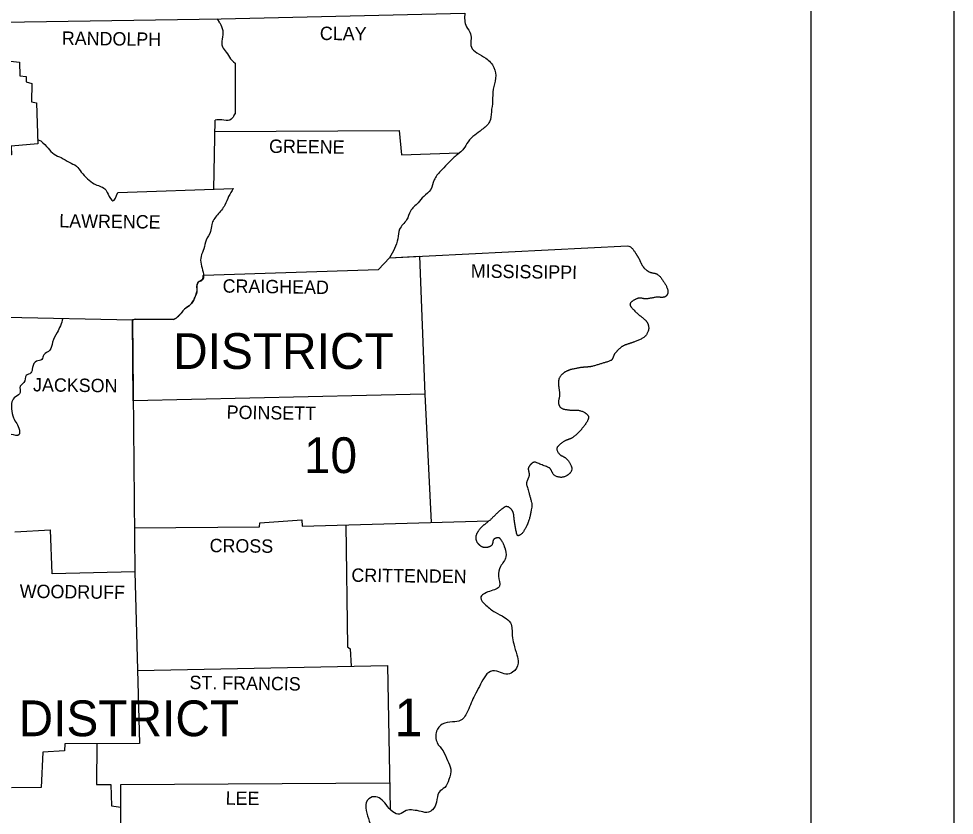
# Model space of a CAD drawing. Extents: x -0.54 to 1.64, y 0 to 0.92.
# Drawn here: x 1.2805 to 1.4167, y 0.7032 to 0.8191 of the extents above; entities that cross this region are included whole.
import ezdxf

# ---------------------------------------------------------------- set-up
doc = ezdxf.new("R2010")
doc.units = 0
for name, color, linetype in [('Default', 7, 'Continuous'), ('SHET_Annotations', 7, 'Continuous'), ('SHET_Border-Lines', 7, 'Continuous')]:
    doc.layers.add(name, color=color, linetype=linetype)

msp = doc.modelspace()

# ---------------------------------------------------------------- linework, layer by layer
at = {"layer": 'Default'}
msp.add_lwpolyline([(1.30741, 0.78176), (1.33287, 0.7826), (1.33448, 0.78431), (1.33888, 0.78453), (1.33964, 0.76447), (1.29721, 0.7635), (1.29711, 0.77526), (1.29752, 0.77536), (1.30307, 0.77533)], dxfattribs=at)
for points, degree in [([(1.3073, 0.78117), (1.30736, 0.78136), (1.3074, 0.78156), (1.30741, 0.78176)], 2), ([(1.30307, 0.77533), (1.30334, 0.77546), (1.30357, 0.77561), (1.30377, 0.7758), (1.30411, 0.77612), (1.30435, 0.77652), (1.30468, 0.77684), (1.30494, 0.77709), (1.30528, 0.77724), (1.30554, 0.77751), (1.30579, 0.77779), (1.30598, 0.7781), (1.30613, 0.77845), (1.30627, 0.77874), (1.30636, 0.77905), (1.30644, 0.77935), (1.30657, 0.77978), (1.30648, 0.78025), (1.3066, 0.78068), (1.30668, 0.78095), (1.30721, 0.78089), (1.3073, 0.78117)], 3)]:
    msp.add_open_spline(points, degree=degree, dxfattribs=at)
at = {"layer": 'SHET_Annotations'}
for p, q in [((1.30981, 0.81849), (1.30946, 0.81908)), ((1.31179, 0.81284), (1.31202, 0.81262)), ((1.31186, 0.80498), (1.31202, 0.80525)), ((1.28383, 0.80129), (1.28329, 0.80145)), ((1.31176, 0.79437), (1.31178, 0.79439)), ((1.27998, 0.74446), (1.28519, 0.74474))]:
    msp.add_line(p, q, dxfattribs=at)
for points in [[(1.09511, 0.81784), (1.16886, 0.81779), (1.23365, 0.81792), (1.31002, 0.81909), (1.34545, 0.81992)], [(1.27561, 0.81856), (1.27545, 0.81717), (1.27636, 0.81704), (1.27628, 0.81652), (1.27735, 0.81628), (1.27742, 0.81553), (1.27794, 0.81522), (1.27807, 0.81304), (1.28066, 0.81278), (1.28069, 0.81079), (1.28165, 0.81068), (1.28162, 0.8099), (1.28245, 0.80965), (1.28243, 0.807), (1.28313, 0.80687), (1.28331, 0.80091), (1.27945, 0.80054), (1.2795, 0.79927), (1.27833, 0.79919), (1.27872, 0.77567), (1.29711, 0.77526), (1.29742, 0.73864), (1.28541, 0.73833), (1.28519, 0.74474)], [(1.31202, 0.81262), (1.31202, 0.80525)], [(1.30892, 0.7943), (1.30914, 0.80435)], [(1.3091, 0.80269), (1.33588, 0.80282), (1.33624, 0.79927), (1.3446, 0.79956)], [(1.29495, 0.79383), (1.31178, 0.79439)], [(1.33448, 0.78431), (1.36913, 0.78605)], [(1.30741, 0.78176), (1.33287, 0.7826), (1.33448, 0.78431)], [(1.33888, 0.78453), (1.33964, 0.76447), (1.34056, 0.74579)], [(1.30307, 0.77533), (1.29752, 0.77536), (1.29711, 0.77526)], [(1.33964, 0.76447), (1.29721, 0.7635)], [(1.29736, 0.74504), (1.31557, 0.74515), (1.31562, 0.74577), (1.32174, 0.74621), (1.32177, 0.74528), (1.34896, 0.74602)], [(1.32812, 0.74545), (1.32838, 0.72769), (1.32877, 0.72741), (1.32894, 0.72492)], [(1.29742, 0.73864), (1.29812, 0.71366), (1.28725, 0.71361), (1.2872, 0.7126), (1.28406, 0.71239), (1.2838, 0.70723), (1.27948, 0.7072)], [(1.29782, 0.72429), (1.33419, 0.72502)], [(1.33419, 0.72502), (1.33457, 0.70412)], [(1.29192, 0.71363), (1.29184, 0.7077), (1.29394, 0.7077), (1.29405, 0.70456), (1.29542, 0.7044)], [(1.29192, 0.71363), (1.29184, 0.7077), (1.29394, 0.7077), (1.29405, 0.70456), (1.29542, 0.7044)], [(1.29727, 0.6672), (1.30154, 0.66747), (1.30152, 0.67671), (1.29814, 0.67697), (1.29833, 0.69507), (1.29547, 0.69548), (1.2954, 0.70767), (1.3345, 0.70793)]]:
    msp.add_lwpolyline(points, dxfattribs=at)
for points in [[(1.34545, 0.81992), (1.34568, 0.81792), (1.3463, 0.81688), (1.34641, 0.81496), (1.34719, 0.81413), (1.34851, 0.81333), (1.34968, 0.81198), (1.34994, 0.81042), (1.34957, 0.80884), (1.34949, 0.80708), (1.34931, 0.80552), (1.34905, 0.8041), (1.34794, 0.80295), (1.3469, 0.80215), (1.34594, 0.80119), (1.34527, 0.80015), (1.34405, 0.79906), (1.34288, 0.79792), (1.34192, 0.79691), (1.34099, 0.79564), (1.3405, 0.79424), (1.33948, 0.79323), (1.33865, 0.79232), (1.33754, 0.7911), (1.33699, 0.78983), (1.33596, 0.78846), (1.3357, 0.78708), (1.33448, 0.78431)], [(1.30981, 0.81849), (1.31023, 0.81737), (1.31015, 0.81613), (1.31018, 0.81501), (1.31075, 0.81421), (1.31137, 0.81325), (1.31179, 0.81284)], [(1.31186, 0.80498), (1.31127, 0.80435), (1.3101, 0.80438), (1.30914, 0.80435)], [(1.28383, 0.80129), (1.28481, 0.80026), (1.28572, 0.79938), (1.28671, 0.79888), (1.2879, 0.79821), (1.28894, 0.79764), (1.28964, 0.79678), (1.29057, 0.79582), (1.29153, 0.79507), (1.29306, 0.79434), (1.29355, 0.79357), (1.29425, 0.79261), (1.29495, 0.79383)], [(1.31176, 0.79437), (1.31109, 0.79325), (1.31054, 0.79198), (1.30945, 0.79056), (1.30862, 0.78913), (1.30847, 0.78815), (1.30782, 0.78688), (1.30748, 0.78563), (1.30707, 0.78452), (1.30707, 0.78337), (1.30738, 0.78223), (1.3073, 0.78117), (1.3066, 0.78068), (1.30644, 0.77935), (1.30613, 0.77845), (1.30554, 0.77751), (1.30468, 0.77684), (1.30377, 0.7758), (1.30307, 0.77533)], [(1.28698, 0.77549), (1.28614, 0.77342), (1.28546, 0.77204), (1.28507, 0.77085), (1.28419, 0.77017), (1.28391, 0.76953), (1.28315, 0.76927), (1.28256, 0.76836), (1.2823, 0.76755), (1.28165, 0.76719), (1.28131, 0.76615), (1.28074, 0.76561), (1.28077, 0.7647), (1.28009, 0.76408), (1.27955, 0.76335), (1.27952, 0.76232), (1.27978, 0.76102), (1.28025, 0.76021), (1.28064, 0.75923), (1.28061, 0.75858), (1.27947, 0.75858), (1.27849, 0.75843)], [(1.35126, 0.74211), (1.35144, 0.74082), (1.35064, 0.73939), (1.35035, 0.73799), (1.35051, 0.73656), (1.34905, 0.73578), (1.34776, 0.73485), (1.34851, 0.73379), (1.34986, 0.73275), (1.35123, 0.732), (1.35209, 0.73119), (1.35235, 0.72935), (1.35258, 0.72813), (1.35302, 0.72653), (1.3532, 0.72536), (1.3524, 0.72401), (1.35144, 0.72373), (1.3504, 0.72406), (1.34921, 0.72414), (1.34825, 0.72321), (1.34758, 0.72196), (1.3469, 0.72067), (1.34638, 0.71958), (1.34589, 0.71841), (1.34488, 0.71703), (1.34366, 0.7168), (1.34218, 0.71644), (1.34133, 0.71543), (1.34145, 0.71374), (1.34228, 0.71257), (1.34293, 0.71117), (1.3434, 0.70993), (1.34314, 0.7084), (1.34252, 0.70726), (1.34171, 0.70656), (1.34133, 0.7051), (1.34075, 0.70402), (1.34018, 0.70365), (1.33909, 0.70376), (1.33793, 0.70396), (1.33692, 0.70389), (1.33593, 0.70337), (1.33497, 0.7037), (1.33399, 0.70477), (1.33318, 0.7056), (1.33225, 0.70591), (1.33129, 0.70542), (1.33111, 0.70391), (1.33155, 0.70236), (1.33199, 0.70025), (1.33157, 0.69901), (1.33142, 0.69688)]]:
    msp.add_spline(points, degree=3, dxfattribs=at)
msp.add_open_spline([(1.36913, 0.78605), (1.3693, 0.78602), (1.36947, 0.78595), (1.36962, 0.78584), (1.36978, 0.78572), (1.3699, 0.78558), (1.37001, 0.78543), (1.37012, 0.78526), (1.37024, 0.78509), (1.37034, 0.78492), (1.37039, 0.78483), (1.37045, 0.78474), (1.3705, 0.78466), (1.37055, 0.78458), (1.3706, 0.78449), (1.37066, 0.78441), (1.37073, 0.7843), (1.37079, 0.78419), (1.37085, 0.78407), (1.3709, 0.78395), (1.37095, 0.78383), (1.37101, 0.78372), (1.37106, 0.7836), (1.37112, 0.78348), (1.37117, 0.78336), (1.37123, 0.78325), (1.3713, 0.78314), (1.37138, 0.78304), (1.37165, 0.78271), (1.37197, 0.78246), (1.37234, 0.78226), (1.37243, 0.78221), (1.37253, 0.78217), (1.37263, 0.78215), (1.37273, 0.78212), (1.37283, 0.7821), (1.37293, 0.78208), (1.37304, 0.78206), (1.37314, 0.78204), (1.37324, 0.78201), (1.37334, 0.78198), (1.37343, 0.78194), (1.37351, 0.78187), (1.37388, 0.78158), (1.37414, 0.78123), (1.37439, 0.78083), (1.37463, 0.78046), (1.37483, 0.78009), (1.37496, 0.77967), (1.37499, 0.77958), (1.375, 0.77949), (1.375, 0.77941), (1.375, 0.77932), (1.37499, 0.77923), (1.37497, 0.77913), (1.37494, 0.77904), (1.37491, 0.77896), (1.37486, 0.77888), (1.37483, 0.77884), (1.3748, 0.7788), (1.37477, 0.77877), (1.37475, 0.77875), (1.37473, 0.77874), (1.37471, 0.77872), (1.37469, 0.77871), (1.37467, 0.77869), (1.37465, 0.77868), (1.37455, 0.77862), (1.37444, 0.77858), (1.37433, 0.77856), (1.37422, 0.77855), (1.37411, 0.77855), (1.374, 0.77855), (1.37389, 0.77856), (1.37379, 0.77858), (1.37368, 0.77858), (1.37362, 0.77859), (1.37357, 0.77859), (1.37351, 0.77859), (1.37346, 0.77859), (1.37341, 0.77859), (1.37335, 0.77858), (1.37312, 0.77854), (1.37289, 0.7785), (1.37265, 0.77846), (1.37242, 0.77842), (1.37219, 0.77838), (1.37195, 0.77834), (1.37184, 0.77833), (1.37173, 0.77833), (1.37162, 0.77835), (1.37151, 0.77836), (1.37139, 0.77839), (1.37128, 0.77841), (1.37117, 0.77842), (1.37106, 0.77844), (1.37094, 0.77845), (1.37089, 0.77845), (1.37083, 0.77845), (1.37077, 0.77844), (1.37072, 0.77843), (1.37066, 0.77841), (1.3706, 0.77839), (1.37047, 0.77835), (1.37035, 0.77829), (1.37022, 0.77823), (1.37009, 0.77817), (1.36996, 0.77809), (1.36984, 0.77801), (1.36974, 0.77794), (1.36965, 0.77786), (1.36957, 0.77776), (1.36953, 0.77772), (1.36951, 0.77767), (1.3695, 0.77762), (1.36949, 0.7776), (1.36949, 0.77758), (1.36949, 0.77755), (1.36948, 0.77753), (1.36948, 0.77751), (1.36949, 0.77749), (1.36952, 0.77738), (1.36956, 0.77728), (1.36963, 0.77718), (1.36971, 0.77707), (1.36979, 0.77697), (1.36988, 0.77687), (1.37008, 0.77667), (1.37029, 0.77646), (1.3705, 0.77627), (1.37061, 0.77617), (1.37072, 0.77607), (1.37083, 0.77598), (1.37094, 0.77589), (1.37106, 0.7758), (1.37117, 0.77571), (1.37128, 0.77563), (1.37139, 0.77554), (1.37151, 0.77544), (1.37162, 0.77535), (1.37172, 0.77524), (1.37182, 0.77513), (1.3719, 0.77504), (1.37196, 0.77494), (1.37202, 0.77484), (1.37207, 0.77474), (1.37211, 0.77463), (1.37215, 0.77452), (1.37218, 0.77441), (1.3722, 0.7743), (1.3722, 0.77419), (1.37221, 0.77409), (1.37221, 0.77399), (1.37219, 0.77388), (1.37214, 0.77365), (1.37206, 0.77344), (1.37194, 0.77323), (1.37188, 0.77312), (1.3718, 0.77302), (1.37172, 0.77293), (1.37163, 0.77284), (1.37154, 0.77276), (1.37143, 0.77269), (1.37121, 0.77255), (1.37097, 0.77242), (1.37073, 0.77232), (1.37049, 0.77223), (1.37025, 0.77213), (1.37001, 0.77204), (1.36989, 0.772), (1.36977, 0.77195), (1.36965, 0.77191), (1.36952, 0.77187), (1.3694, 0.77183), (1.36928, 0.77179), (1.36916, 0.77175), (1.36904, 0.77171), (1.36891, 0.77167), (1.36879, 0.77163), (1.36867, 0.77158), (1.36856, 0.77152), (1.36843, 0.77146), (1.36831, 0.77139), (1.3682, 0.7713), (1.36809, 0.77122), (1.36798, 0.77113), (1.36788, 0.77103), (1.36778, 0.77093), (1.36769, 0.77082), (1.36759, 0.77072), (1.3675, 0.77062), (1.3674, 0.77051), (1.36731, 0.77041), (1.36724, 0.77033), (1.36719, 0.77024), (1.36715, 0.77014), (1.36711, 0.77004), (1.36708, 0.76994), (1.36704, 0.76984), (1.367, 0.76974), (1.36696, 0.76965), (1.36691, 0.76956), (1.36685, 0.76948), (1.36678, 0.76941), (1.36669, 0.76937), (1.36646, 0.76927), (1.36623, 0.76918), (1.36599, 0.76911), (1.36576, 0.76904), (1.36552, 0.76897), (1.36529, 0.7689), (1.36505, 0.76883), (1.36481, 0.76875), (1.36457, 0.76868), (1.36432, 0.76861), (1.36408, 0.76854), (1.36384, 0.76849), (1.36373, 0.76846), (1.36362, 0.76845), (1.36351, 0.76844), (1.36341, 0.76843), (1.3633, 0.76842), (1.36319, 0.76841), (1.36308, 0.7684), (1.36297, 0.7684), (1.36286, 0.76839), (1.36276, 0.76838), (1.36265, 0.76837), (1.36254, 0.76836), (1.3623, 0.76833), (1.36206, 0.76829), (1.36182, 0.76824), (1.36159, 0.7682), (1.36135, 0.76815), (1.36111, 0.7681), (1.36098, 0.76807), (1.36085, 0.76804), (1.36073, 0.768), (1.3606, 0.76796), (1.36048, 0.76791), (1.36036, 0.76786), (1.36024, 0.7678), (1.36012, 0.76774), (1.36, 0.76767), (1.35994, 0.76763), (1.35989, 0.76758), (1.35983, 0.76754), (1.35977, 0.7675), (1.35972, 0.76745), (1.35966, 0.7674), (1.35949, 0.76724), (1.35934, 0.76705), (1.35922, 0.76684), (1.35917, 0.76674), (1.35913, 0.76664), (1.35911, 0.76653), (1.35908, 0.76642), (1.35906, 0.76631), (1.35906, 0.76621), (1.35906, 0.76607), (1.35907, 0.76592), (1.35909, 0.76578), (1.3591, 0.76564), (1.35912, 0.7655), (1.35914, 0.76536), (1.35916, 0.76522), (1.35918, 0.76508), (1.3592, 0.76494), (1.35922, 0.7648), (1.35924, 0.76466), (1.35925, 0.76452), (1.35925, 0.76437), (1.35923, 0.76423), (1.35921, 0.76408), (1.35919, 0.76393), (1.35914, 0.76379), (1.35912, 0.76364), (1.35909, 0.76349), (1.35908, 0.76334), (1.35908, 0.7632), (1.35909, 0.76312), (1.3591, 0.76305), (1.35912, 0.76298), (1.35913, 0.76294), (1.35915, 0.7629), (1.35916, 0.76287), (1.35918, 0.76283), (1.3592, 0.76279), (1.35922, 0.76276), (1.35929, 0.76263), (1.35939, 0.76253), (1.35951, 0.76245), (1.35963, 0.76237), (1.35976, 0.76232), (1.35989, 0.76229), (1.36003, 0.76226), (1.36017, 0.76224), (1.36031, 0.76222), (1.36045, 0.7622), (1.36058, 0.76218), (1.36072, 0.76216), (1.36083, 0.76215), (1.36094, 0.76213), (1.36105, 0.76213), (1.36116, 0.76213), (1.36127, 0.76214), (1.36139, 0.76214), (1.3615, 0.76214), (1.36161, 0.76214), (1.36172, 0.76214), (1.36183, 0.76215), (1.36194, 0.76213), (1.36205, 0.76211), (1.36229, 0.76206), (1.36253, 0.76198), (1.36275, 0.76187), (1.36287, 0.76182), (1.36297, 0.76175), (1.36307, 0.76167), (1.36312, 0.76164), (1.36317, 0.76159), (1.36321, 0.76155), (1.36326, 0.76151), (1.3633, 0.76146), (1.36334, 0.76141), (1.3634, 0.76134), (1.36343, 0.76125), (1.36344, 0.76117), (1.36346, 0.76108), (1.36345, 0.76099), (1.36342, 0.7609), (1.36336, 0.76072), (1.36329, 0.76055), (1.36319, 0.7604), (1.36304, 0.76018), (1.3629, 0.75996), (1.36274, 0.75976), (1.36266, 0.75965), (1.36258, 0.75955), (1.36249, 0.75945), (1.36241, 0.75935), (1.36232, 0.75925), (1.36223, 0.75915), (1.36189, 0.75878), (1.36152, 0.75844), (1.36111, 0.75814), (1.36103, 0.75808), (1.36094, 0.75803), (1.36084, 0.75799), (1.36075, 0.75795), (1.36065, 0.75792), (1.36055, 0.75788), (1.36046, 0.75785), (1.36036, 0.75782), (1.36026, 0.75778), (1.36016, 0.75775), (1.36006, 0.7577), (1.35997, 0.75765), (1.35975, 0.75752), (1.35955, 0.75737), (1.35935, 0.75721), (1.35925, 0.75713), (1.35917, 0.75705), (1.35909, 0.75696), (1.35901, 0.75688), (1.35894, 0.75679), (1.35888, 0.75669), (1.35881, 0.75655), (1.35884, 0.75635), (1.35891, 0.7562), (1.359, 0.75603), (1.3591, 0.75586), (1.35925, 0.75573), (1.35932, 0.75566), (1.35939, 0.75559), (1.35948, 0.75554), (1.35957, 0.7555), (1.35966, 0.75545), (1.35974, 0.75541), (1.35983, 0.75536), (1.35991, 0.75531), (1.36, 0.75526), (1.36009, 0.75522), (1.36016, 0.75515), (1.36023, 0.75508), (1.36054, 0.75478), (1.36076, 0.75442), (1.36091, 0.75404), (1.36102, 0.75375), (1.36102, 0.75335), (1.36083, 0.75308), (1.36079, 0.75303), (1.36075, 0.75299), (1.36071, 0.75295), (1.36067, 0.7529), (1.36063, 0.75286), (1.36058, 0.75283), (1.3605, 0.75275), (1.36041, 0.75269), (1.36032, 0.75263), (1.36014, 0.75252), (1.35994, 0.75246), (1.35974, 0.75241), (1.35954, 0.75236), (1.35932, 0.75237), (1.35912, 0.7524), (1.35891, 0.75244), (1.35871, 0.75251), (1.35852, 0.75264), (1.35841, 0.75272), (1.35833, 0.7528), (1.35827, 0.75291), (1.35821, 0.75302), (1.35816, 0.75313), (1.3581, 0.75324), (1.35804, 0.75335), (1.35799, 0.75346), (1.35792, 0.75356), (1.35786, 0.75366), (1.35777, 0.75374), (1.35766, 0.75378), (1.35734, 0.75393), (1.357, 0.75404), (1.35668, 0.75417), (1.35638, 0.7543), (1.35609, 0.75444), (1.3558, 0.75456), (1.35571, 0.75459), (1.35562, 0.7546), (1.35553, 0.75458), (1.35544, 0.75455), (1.35535, 0.75451), (1.35527, 0.75445), (1.35518, 0.75439), (1.3551, 0.75432), (1.35503, 0.75424), (1.35499, 0.75419), (1.35495, 0.75415), (1.35491, 0.7541), (1.35488, 0.75406), (1.35484, 0.75401), (1.35481, 0.75396), (1.35475, 0.75387), (1.3547, 0.75375), (1.35469, 0.75364), (1.35469, 0.75353), (1.3547, 0.75342), (1.35472, 0.75331), (1.35475, 0.7532), (1.35478, 0.7531), (1.3548, 0.75299), (1.35481, 0.75293), (1.35481, 0.75288), (1.35482, 0.75283), (1.35482, 0.75277), (1.35482, 0.75272), (1.35481, 0.75267), (1.35479, 0.75254), (1.35475, 0.75243), (1.35471, 0.75231), (1.35466, 0.75219), (1.3546, 0.75207), (1.35456, 0.75195), (1.35451, 0.75184), (1.35447, 0.75172), (1.35444, 0.7516), (1.35442, 0.75148), (1.35442, 0.75136), (1.35445, 0.75124), (1.35455, 0.75089), (1.35466, 0.75053), (1.35476, 0.75018), (1.35489, 0.7497), (1.35503, 0.74923), (1.35515, 0.74875), (1.35524, 0.7484), (1.35518, 0.74802), (1.35512, 0.74766), (1.35503, 0.74713), (1.35492, 0.7466), (1.35476, 0.74608), (1.35471, 0.74594), (1.35467, 0.7458), (1.35461, 0.74566), (1.35455, 0.74552), (1.35449, 0.74539), (1.35443, 0.74526), (1.35436, 0.74512), (1.35429, 0.74499), (1.35421, 0.74486), (1.35414, 0.74473), (1.35406, 0.7446), (1.35398, 0.74447), (1.35386, 0.74428), (1.35369, 0.74414), (1.3535, 0.74399), (1.35341, 0.74393), (1.35332, 0.7439), (1.35323, 0.74388), (1.3532, 0.74387), (1.35317, 0.74387), (1.35313, 0.7439), (1.3531, 0.74392), (1.35308, 0.74395), (1.35307, 0.74398), (1.35299, 0.74426), (1.35291, 0.74455), (1.35286, 0.74484), (1.35281, 0.74513), (1.35275, 0.74542), (1.35271, 0.74572), (1.35268, 0.74595), (1.35265, 0.74618), (1.35263, 0.74642), (1.35261, 0.74653), (1.3526, 0.74665), (1.35258, 0.74677), (1.35257, 0.74689), (1.35255, 0.747), (1.35253, 0.74712), (1.35251, 0.7472), (1.35249, 0.74728), (1.35246, 0.74735), (1.35242, 0.74743), (1.35239, 0.7475), (1.35234, 0.74757), (1.35229, 0.74764), (1.35224, 0.7477), (1.35218, 0.74777), (1.35212, 0.74783), (1.35206, 0.74789), (1.35198, 0.74795), (1.35187, 0.74804), (1.35174, 0.74809), (1.35161, 0.7481), (1.35148, 0.74812), (1.35134, 0.7481), (1.35123, 0.74803), (1.35115, 0.74797), (1.35107, 0.74792), (1.35099, 0.74786), (1.35091, 0.7478), (1.35083, 0.74775), (1.35075, 0.74769), (1.35059, 0.74756), (1.35044, 0.74744), (1.3503, 0.7473), (1.35012, 0.74713), (1.34994, 0.74695), (1.34977, 0.74678), (1.34959, 0.74661), (1.34941, 0.74643), (1.34923, 0.74626), (1.34913, 0.74616), (1.34902, 0.74607), (1.34891, 0.74598), (1.3488, 0.74589), (1.34869, 0.7458), (1.34858, 0.74571), (1.34847, 0.74562), (1.34836, 0.74553), (1.34824, 0.74544), (1.34813, 0.74534), (1.34802, 0.74525), (1.34791, 0.74515), (1.34773, 0.74498), (1.34758, 0.74479), (1.34744, 0.74459), (1.34737, 0.74449), (1.34731, 0.74439), (1.34726, 0.74429), (1.3472, 0.74419), (1.34715, 0.74409), (1.34711, 0.74398), (1.34706, 0.74387), (1.34704, 0.74375), (1.34703, 0.74364), (1.34703, 0.74352), (1.34704, 0.74339), (1.34709, 0.74327), (1.34713, 0.74313), (1.34718, 0.74301), (1.34726, 0.7429), (1.3473, 0.74283), (1.34734, 0.74278), (1.34739, 0.74272), (1.34741, 0.74269), (1.34744, 0.74266), (1.34747, 0.74264), (1.34749, 0.74261), (1.34752, 0.74258), (1.34755, 0.74255), (1.34763, 0.74248), (1.34771, 0.74242), (1.3478, 0.74237), (1.34788, 0.74232), (1.34797, 0.74228), (1.34805, 0.74226), (1.34814, 0.74223), (1.34822, 0.74221), (1.34831, 0.7422), (1.34839, 0.74219), (1.34848, 0.74219), (1.34856, 0.74219), (1.34863, 0.74219), (1.34869, 0.7422), (1.34876, 0.74221), (1.34882, 0.74223), (1.34889, 0.74225), (1.34895, 0.74227), (1.34902, 0.7423), (1.34908, 0.74233), (1.34914, 0.74236), (1.34921, 0.74239), (1.34928, 0.74243), (1.34934, 0.74248), (1.34941, 0.74253), (1.34947, 0.7426), (1.3495, 0.74268), (1.34953, 0.74276), (1.34955, 0.74285), (1.34956, 0.74294), (1.34958, 0.74303), (1.34959, 0.74311), (1.34961, 0.7432), (1.34963, 0.74328), (1.34967, 0.74335), (1.34973, 0.74341), (1.34978, 0.74346), (1.34984, 0.7435), (1.3499, 0.74353), (1.34997, 0.74357), (1.35005, 0.74359), (1.35012, 0.74361), (1.35019, 0.74363), (1.35027, 0.74364), (1.35034, 0.74363), (1.3504, 0.74361), (1.35046, 0.74359), (1.35051, 0.74354), (1.35055, 0.74349), (1.35059, 0.74344), (1.35063, 0.74338), (1.35067, 0.74333), (1.35071, 0.74327), (1.35075, 0.74322), (1.35082, 0.74311), (1.35089, 0.74299), (1.35095, 0.74287), (1.35108, 0.74263), (1.35117, 0.74237), (1.35126, 0.74211)], degree=3, dxfattribs=at)
at = {"layer": 'SHET_Border-Lines'}
for points in [[(0, 0), (1.41667, 0), (1.41667, 0.91667), (0, 0.91667)], [(0.04167, 0.02083), (1.39583, 0.02083), (1.39583, 0.89583), (0.04167, 0.89583)]]:
    msp.add_lwpolyline(points, close=True, dxfattribs=at)

# ---------------------------------------------------------------- texts
at = {"layer": 'SHET_Annotations'}
for s, height, rotation, p in [('RANDOLPH', 0.001945, 359.2573, (1.28681, 0.8153)), ('CLAY', 0.001945, 359.3364, (1.32435, 0.816)), ('GREENE', 0.001945, 359.2711, (1.31696, 0.79958)), ('LAWRENCE', 0.001945, 359.2655, (1.28644, 0.78873)), ('MISSISSIPPI', 0.0019451, 359.2098, (1.34631, 0.78143)), ('CRAIGHEAD', 0.001945, 359.1888, (1.3102, 0.77925)), ('JACKSON', 0.001945, 359.2575, (1.28262, 0.76488)), ('POINSETT', 0.001945, 359.1979, (1.31079, 0.76089)), ('CROSS', 0.001945, 359.3097, (1.30831, 0.74149)), ('CRITTENDEN', 0.001945, 359.2782, (1.32894, 0.73718)), ('WOODRUFF', 0.001945, 359.2708, (1.28068, 0.73485)), ('ST. FRANCIS', 0.0019451, 359.1956, (1.30538, 0.72157)), ('ST. FRANCIS', 0.0019451, 359.1956, (1.30538, 0.72157)), ('LEE', 0.001945, 359.3634, (1.31065, 0.70474))]:
    msp.add_text(s, height=height, rotation=rotation, dxfattribs=at).set_placement(p)
for s, height, p in [('DISTRICT', 0.005203, (1.30302, 0.76814)), ('10', 0.005203, (1.32204, 0.75299)), ('1', 0.00548, (1.33522, 0.71471)), ('DISTRICT', 0.005203, (1.28053, 0.71471))]:
    msp.add_text(s, height=height, dxfattribs=at).set_placement(p)

doc.saveas('drawing.dxf')
